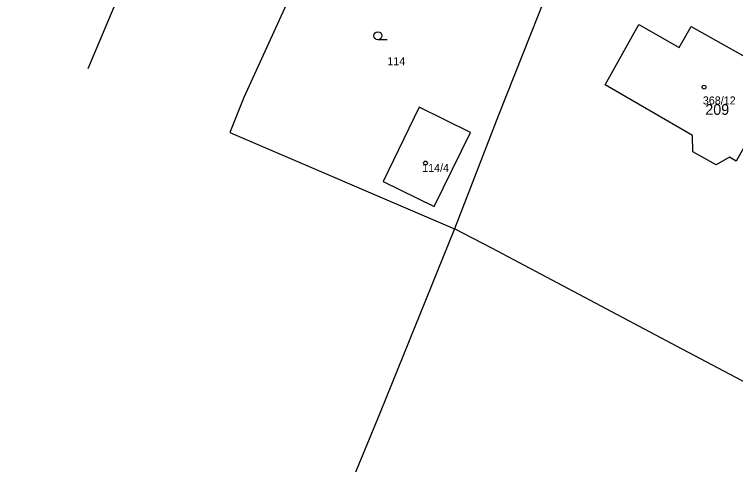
# Model space of a CAD drawing. Extents: x -836568 to -836015, y -1070547 to -1070212.
# Drawn here: x -836490.6 to -836423.1, y -1070434.3 to -1070392.2 of the extents above; entities that cross this region are included whole.
import ezdxf

# ---------------------------------------------------------------- set-up
doc = ezdxf.new("R2010")
doc.units = 0
for name, color, linetype in [('BodPole_mer', 7, 'Continuous'), ('Budovy_hranice', 7, 'Continuous'), ('Budovy_kody', 7, 'Continuous'), ('OstPloch_kody', 7, 'Continuous'), ('RuianAdr_popis', 7, 'Continuous'), ('RuianPar_popis', 7, 'Continuous'), ('Stavby_linie', 7, 'Continuous')]:
    doc.layers.add(name, color=color, linetype=linetype)

msp = doc.modelspace()

# ---------------------------------------------------------------- linework, layer by layer
at = {"layer": 'BodPole_mer'}
for p, q in [((-836432.13, -1070393.14), (-836432.13, -1070393.14)), ((-836427.22, -1070393.31), (-836427.22, -1070393.31)), ((-836428.33, -1070395.3), (-836428.33, -1070395.3)), ((-836435.26, -1070398.78), (-836435.26, -1070398.78)), ((-836452.68, -1070400.88), (-836452.68, -1070400.88)), ((-836445.25, -1070401.61), (-836445.25, -1070401.61)), ((-836447.89, -1070403.24), (-836447.89, -1070403.24)), ((-836427.09, -1070403.54), (-836427.09, -1070403.54)), ((-836427.06, -1070405.06), (-836427.06, -1070405.06)), ((-836423.64, -1070405.55), (-836423.64, -1070405.55)), ((-836424.86, -1070406.28), (-836424.86, -1070406.28)), ((-836456.06, -1070407.83), (-836456.06, -1070407.83)), ((-836451.29, -1070410.18), (-836451.29, -1070410.18)), ((-836449.39, -1070412.25), (-836449.39, -1070412.25)), ((-836445.87, -1070414.08), (-836445.87, -1070414.08)), ((-836428, -1070423.55), (-836428, -1070423.55))]:
    msp.add_line(p, q, dxfattribs=at)
at = {"layer": 'Budovy_hranice'}
for points in [[(-836427.22, -1070393.31), (-836418.61, -1070398.15), (-836419.94, -1070400.5), (-836419.12, -1070401.9), (-836420.07, -1070403.62), (-836421.72, -1070403.64), (-836423.01, -1070405.92), (-836423.64, -1070405.55), (-836424.86, -1070406.28), (-836427.06, -1070405.06), (-836427.09, -1070403.54), (-836435.26, -1070398.78), (-836432.13, -1070393.14), (-836428.33, -1070395.3), (-836427.22, -1070393.31)], [(-836456.06, -1070407.83), (-836451.29, -1070410.18), (-836447.89, -1070403.24), (-836452.68, -1070400.88), (-836456.06, -1070407.83)]]:
    msp.add_lwpolyline(points, dxfattribs=at)
at = {"layer": 'Budovy_kody'}
for centre in [(-836426.01, -1070399), (-836452.09, -1070406.1)]:
    msp.add_circle(centre, 0.175, dxfattribs=at)
at = {"layer": 'OstPloch_kody'}
msp.add_line((-836455.675, -1070394.56), (-836456.55, -1070394.56), dxfattribs=at)
msp.add_ellipse((-836456.55, -1070394.185), major_axis=(0.375, 0), ratio=0.999999, dxfattribs=at)
at = {"layer": 'RuianAdr_popis'}
msp.add_line((-836425.89, -1070401.59), (-836425.89, -1070401.59), dxfattribs=at)
at = {"layer": 'RuianPar_popis'}
for p, q in [((-836455.66, -1070396.95), (-836455.66, -1070396.95)), ((-836426.12, -1070400.62), (-836426.12, -1070400.62)), ((-836452.4, -1070406.93), (-836452.4, -1070406.93))]:
    msp.add_line(p, q, dxfattribs=at)
at = {"layer": 'Stavby_linie'}
msp.add_line((-836470.4, -1070403.24), (-836449.39, -1070412.25), dxfattribs=at)
for points in [[(-836451.09, -1070365.35), (-836457.52, -1070375.69), (-836459.45, -1070378.71), (-836464.64, -1070390.16), (-836469.09, -1070399.98), (-836470.4, -1070403.24)], [(-836483.68, -1070397.24), (-836475.54, -1070377.9), (-836480.96, -1070376.27), (-836487.78, -1070373.92), (-836490.58, -1070372.96)], [(-836435.05, -1070376.27), (-836438.54, -1070384.68), (-836445.25, -1070401.61), (-836449.39, -1070412.25)], [(-836449.39, -1070412.25), (-836456.32, -1070429.46), (-836463.2, -1070446.07), (-836469.22, -1070461.85), (-836476.75, -1070482.14), (-836479.99, -1070490.54)], [(-836407.72, -1070434.26), (-836415.3, -1070430.25), (-836428, -1070423.55), (-836445.87, -1070414.08), (-836449.39, -1070412.25)]]:
    msp.add_lwpolyline(points, dxfattribs=at)

# ---------------------------------------------------------------- texts
at = {"layer": 'RuianAdr_popis'}
msp.add_text('209', height=1, dxfattribs=at).set_placement((-836425.89, -1070401.59))
at = {"layer": 'RuianPar_popis'}
for s, p in [('114', (-836455.66, -1070396.95)), ('368/12', (-836426.12, -1070400.62)), ('114/4', (-836452.4, -1070406.93))]:
    msp.add_text(s, height=0.75, dxfattribs=at).set_placement(p)

doc.saveas('drawing.dxf')
